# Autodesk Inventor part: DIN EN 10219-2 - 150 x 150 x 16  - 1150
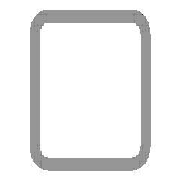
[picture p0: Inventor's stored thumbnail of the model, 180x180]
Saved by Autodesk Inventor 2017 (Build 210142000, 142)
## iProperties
Created: 2017-11
Part Number: DIN EN 10219-2 - 150 x 150 x 16  - 1150
Material: Steel, Mild
Description: Cold formed welded structural hollow sections of non-alloy and fine grain structural steel
Document SubType Name: Modeling
Standard: DIN
Designer: iusti
Standard Revision: 2006-07
Standards Organization: DIN
Language: en-US
Size Designation: 150 x 150 x 16
Categories: <MemberInstance><Categories><Category DisplayName="Structural Shapes" InternalName="089c4875-fa83-4c05-b084-43b9cc11f5ed" Mnemonic="GRDR"><CategoryParameter Dis
Stock Number: 150 x 150 x 16
Mass: 58696.3 g
Surface Area: 9558.04 cm^2
Volume: 7477.24 cm^3
Density: 7.85 g/cm^3
Appearance: Semi-Polished
IsCustomPart: 1
G_W: 150.000 mm
G_H: 150.000 mm
G_L: 1150.000 mm
+D0655DDE-97F9-4B99-A490-E36C02108510+CUTDETAIL1: Miter 45.00 deg
+B95BDB02-C4C2-4ECB-9363-19BA39C44CCB+CUTDETAIL2: Miter 45.00 deg
_CCFamilyMember: 76
_CCFamilyDisplayName: DIN EN 10219-2 (Square Hollow Section - Cold Formed) - Cold formed welded structural hollow sections of non-alloy and fine grain structural steel
_FrameMemberDoc: Frame Member File
_Version: 15.0.0
_GetPNFromCC: 1
Author: iusti
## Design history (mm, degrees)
node "Start plane"
node "End plane"
sketch "Sketch"
  geometry: L1 (-75, -27)-(-75, 27); L2 (-27, 75)-(27, 75); L3 (75, 27)-(75, -27); L4 (27, -75)-(-27, -75); L5 (-27, 59)-(27, 59); L6 (59, 27)-(59, -27); L7 (27, -59)-(-27, -59); L8 (-59, -27)-(-59, 27); L9 (0, 118.918)-(0, -118.918) reference; L10 (-118.918, 0)-(118.918, 0) reference; A1 r 48 centre (-27, -27) between (-75, -27) and (-27, -75); A2 r 48 centre (-27, 27) between (-27, 75) and (-75, 27); A3 r 48 centre (27, 27) between (75, 27) and (27, 75); A4 r 48 centre (27, -27) between (27, -75) and (75, -27); A5 r 32 centre (-27, 27) between (-27, 59) and (-59, 27); A6 r 32 centre (27, 27) between (59, 27) and (27, 59); A7 r 32 centre (27, -27) between (27, -59) and (59, -27); A8 r 32 centre (-27, -27) between (-59, -27) and (-27, -59)
  constraints: 16 end point, 16 point on circle, 8 centre point, 8 tangent, 4 parallel, 3 equal radius, 2 perpendicular, 7 other
  dimensions: "d7" = 48 radius of A1 (= G_IR); "d10" = 150 distance between parallel lines of L2 L4 (= G_H); "d11" = 150 distance between parallel lines of L1 L3 (= G_W); "d12" = 16 distance between parallel lines of L3 L6 (= G_T); "d15" = 75 distance between parallel lines of L2 L10 (= 0.5 x d10); "d16" = 75 distance between parallel lines of L9 L3 (= 0.5 x d11)
extrude "Body" new body sketch "Sketch" stored distance "d3" = 1150 (= G_L); taper "d4" = 0 deg
node "Driven Length"
  sketch "Sketch3"
    geometry: L1 (0, 0)-(10, 0) reference
    constraints: 2 end point, 1 horizontal
  workplane "Work Plane3"
  sketch "Sketch4"
    geometry: L1 (-2, -75)-(12, -75) reference; L2 (-2, 1075)-(12, 1075) reference
    dimensions: "d18" = 1150 distance between parallel lines of L1 L2 (derived)
workplane "Work Plane4"
split "Split1"
workplane "Work Plane5"
split "Split2"
body "Solid1"
other parameters: "G_W" = 150 [user parameter; used in 1 equation term], "G_H" = 150 [user parameter; used in 1 equation term], "G_T" = 16 [user parameter; used in 1 equation term], "G_IR" = 48 [user parameter; used in 1 equation term], "G_L" = 1150 (= d18) [user parameter; used in 1 equation term], "G_OFFSET_START" = 75 [user parameter; used in 1 equation term], "G_OFFSET_END" = 75 [user parameter; used in 1 equation term], "d13" = -75 (= -G_OFFSET_START), "d14" = 1075 (= G_OFFSET_END + B_L), "d17" = 90 deg
